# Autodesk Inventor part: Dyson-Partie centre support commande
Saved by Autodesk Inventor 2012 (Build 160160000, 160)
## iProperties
Created: 2012-11
Part Number: Dyson-Partie centre support commande
Material: Default
Document SubType Name: Modeling
Designer: Administrateur
Density: 1 g/cm^3
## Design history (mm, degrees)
node "Dyson-Partie centre support commande1"
node "Dyson-Partie centre support commande"
node "Dyson-Partie centre support commande_1"
node "Dyson-Partie centre support commande_2"
node "Dyson-Partie centre support commande_3"
node "Dyson-Partie centre support commande_4"
node "Dyson-Partie centre support commande_5"
node "Dyson-Partie centre support commande_6"
node "Base1"
node "Base2"
node "Base3"
node "Base4"
node "Base5"
node "Base6"
node "Base7"
